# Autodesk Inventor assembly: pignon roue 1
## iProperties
Author: Administrateur
Created: 2001-04
Part Number: pignon roue 1
Document SubType Name: Assemblage
Designer: Administrateur
Control State: 0
Master: False
Checked Out: False
PropertySet Name: Design Tracking Control
Shininess: 60.0
PropertySet Name: _Private Model Information
Length Units: 11269
Angle Units: 11283
Time Units: 11279
Mass Units: 11290
Length Display Precision: 3
Angle Display Precision: 2
Compacted: False
Density: 0.0
Volumn: 0.0
Area: 0.0
PropertySet Name: Model Information
